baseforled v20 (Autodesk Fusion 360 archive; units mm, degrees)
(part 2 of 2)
sketch "Sketch68" plane through (0, 0, 4.5985) normal (0, 0, -1) x axis (1, 0, 0)
  line L1 (-3.9663, 41.098) -> (-0.6842, 41.0807)
  line L2 (-1.3083, -45.5462) -> (-1.3083, -48.2413)
  line L3 (-3.8307, -45.5462) -> (-1.3083, -45.5462)
  line L4 (-10.6203, -6.5447) -> (-36.7742, -6.5447)
  line L5 (-9.5157, 16.395) -> (-9.5157, 5.9667)
  line L6 (-1.1407, 19.395) -> (-6.5157, 19.395)
  line L7 (-1.1407, 39.4899) -> (-1.1407, 19.395)
  line L8 (15.6483, 40.7878) -> (15.6648, 43.898)
  line L9 (22.3093, 30.545) -> (24.7376, 30.545)
  line L10 (22.3093, 19.395) -> (22.3093, 30.545)
  line L11 (27.6843, 19.395) -> (22.3093, 19.395)
  line L12 (30.6843, -6.5447) -> (30.6843, 16.395)
  line L13 (43.6238, -6.5447) -> (30.6843, -6.5447)
  line L14 (7.6317, -45.5462) -> (10.1393, -45.5462)
  line L15 (7.6317, -48.2916) -> (7.6317, -45.5462)
  arc A1 centre (-6.1467, 43.3016) radius 3.1 clockwise from (-3.9663, 41.098) to (-9.2079, 43.7902)
  arc A2 centre (3.4248, -1.4802) radius 47 clockwise from (-1.3083, -48.2413) to (-9.2079, 43.7902)
  arc A3 centre (-3.8306, -43.6412) radius 1.905 clockwise from (-3.8307, -45.5462) to (-5.4959, -44.5664)
  arc A4 centre (3.4248, -1.4802) radius 44 clockwise from (-5.4959, -44.5664) to (-39.7156, -10.1348)
  arc A5 centre (-36.7742, -9.5447) radius 3 clockwise from (-39.7156, -10.1348) to (-36.7742, -6.5447)
  arc A6 centre (3.4248, -1.4802) radius 14.9303 clockwise from (-10.6203, -6.5447) to (-9.5157, 5.9667)
  arc A7 centre (-6.5157, 16.395) radius 3 clockwise from (-9.5157, 16.395) to (-6.5157, 19.395)
  arc A8 centre (1.8593, 39.4899) radius 3 clockwise from (-1.1407, 39.4899) to (-0.6842, 41.0807)
  arc A9 centre (3.4248, -1.4802) radius 44 clockwise from (15.6483, 40.7878) to (26.297, 36.1078)
  arc A10 centre (24.7376, 33.545) radius 3 clockwise from (26.297, 36.1078) to (24.7376, 30.545)
  arc A11 centre (27.6843, 16.395) radius 3 clockwise from (27.6843, 19.395) to (30.6843, 16.395)
  arc A12 centre (43.6238, -9.5447) radius 3 clockwise from (43.6238, -6.5447) to (46.5652, -10.1348)
  arc A13 centre (3.4248, -1.4802) radius 44 clockwise from (46.5652, -10.1348) to (11.7301, -44.6893)
  arc A14 centre (10.1393, -43.6412) radius 1.905 clockwise from (11.7301, -44.6893) to (10.1393, -45.5462)
  arc A15 centre (3.4248, -1.4802) radius 47 clockwise from (15.6648, 43.898) to (7.6317, -48.2916)
  arc A16 centre (3.4248, -1.4802) radius 44 clockwise from (26.297, 36.1078) to (46.5652, -10.1348)
  arc A17 centre (3.4248, -1.4802) radius 38 clockwise from (23.8793, 30.545) to (41.0858, -6.5447)
  arc A18 centre (38.2354, -1.552) radius 60 clockwise from (-21.5565, -6.5447) to (-3.9663, 41.098)
  arc A19 centre (38.2354, -1.552) radius 66 clockwise from (-27.5755, -6.5447) to (-8.9761, 44.5683)
  arc A20 centre (-6.1467, 43.3016) radius 3.1 clockwise from (-8.8639, 41.8094) to (-8.3271, 45.5052)
  arc A21 centre (-6.1467, 43.3016) radius 3.1 clockwise from (-9.2079, 43.7902) to (-8.3271, 45.5052)
  arc A22 centre (-6.1467, 43.3016) radius 3.1 clockwise from (-3.9663, 41.098) to (-9.2079, 43.7902)
  arc A23 centre (-6.1467, 43.3016) radius 3.1 clockwise from (-3.9663, 41.098) to (-8.8639, 41.8094)
  point P25 (26.297, 36.1078)
  point P44 (26.297, 36.1078)
  point P36 (46.5652, -10.1348)
  point P43 (46.5652, -10.1348)
  point P46 (23.8793, 30.545)
  point P47 (41.0858, -6.5447)
  point P50 (-21.5565, -6.5447)
  point P3 (-3.9663, 41.098)
  point P49 (-3.9663, 41.098)
  point P53 (-27.5755, -6.5447)
  point P52 (-8.9761, 44.5683)
  tangent A9 A16
  coincident P25 P44
  coincident P36 P43
  concentric A16 A17
  coincident L9 P46
  coincident L13 P47
  tangent A1 A18
  coincident L4 P50
  coincident P3 P49
  concentric A18 A19
  coincident L4 P53
  coincident A1 P52
  dimension "d470" distance A16 A17 = 6
  dimension "d471" distance A18 A19 = 6
  dimension "d472" radius A18 = 60
extrude "Extrude36" sketch "Sketch68" profile of A1 A2 L4 A10 L9 L13 A12 A16 A17 A18 A19 A20 A21 A22 A23 blind -5.8
sketch "Sketch70" plane through (0, 0, 89.597) normal (0, 0, 1) x axis (-1, 0, 0)
  curve K1 (-0.0797, -3.4063) -> (-5.8098, -5.6112)
  curve K2 (-5.8098, -5.6112) -> (-6.7654, 0.4537)
  arc A1 centre (-3.4248, -1.4802) radius 3.86 clockwise from (-6.7654, 0.4537) to (-0.0797, -3.4063)
  circle C1 centre (-3.4248, -1.4802) radius 1.5
  circle C2 centre (-6.1985, -2.0551) radius 0.5
  circle C3 centre (-5.4873, -3.3373) radius 0.5
  circle C4 centre (-4.2656, -4.0902) radius 0.5
  dimension "d478" diameter C2 = 1
  dimension "d479" diameter C3 = 1
  dimension "d480" diameter C4 = 1
extrude "Extrude6" cut sketch "Sketch70" profile of C2 C3 C4 against normal blind 68
sketch "Sketch71" plane through (0, 0, 33.597) normal (0, 0, -1) x axis (1, 0, 0)
  circle C1 centre (9.1523, 8.2134) radius 1.5
extrude "Extrude7" cut of existing geometry blind -0.2
sketch "Sketch72" plane through (0, 0, 33.597) normal (0, 0, -1) x axis (1, 0, 0)
  circle C1 centre (9.1523, -10.8392) radius 1.5
  circle C2 centre (9.1523, -10.8392) radius 3.64
  circle C3 centre (9.1523, -10.8392) radius 2.64
  concentric C1 C2
  concentric C2 C3
  dimension "d490" diameter C2 = 7.28
  dimension "d491" diameter C3 = 5.28
extrude "Extrude8" add sketch "Sketch72" profile of C2 C3 against normal blind 4
extrude "Extrude9" cut of existing geometry blind -3.2
extrude "Extrude10" cut of existing geometry blind -3.2
extrude "Extrude11" cut sketch "Sketch71" against normal blind 3.2
sketch "Sketch73" plane through (0, 0, 36.797) normal (0, 0, -1) x axis (1, 0, 0)
  circle C1 centre (-7.3477, -1.3129) radius 1.5
  circle C2 centre (-7.3477, -1.3129) radius 2.64
  circle C3 centre (-7.3477, -1.3129) radius 3.64
  concentric C1 C2
  concentric C2 C3
  dimension "d500" diameter C2 = 5.28
  dimension "d501" diameter C3 = 7.28
sketch "Sketch74" plane through (0, 0, 36.797) normal (0, 0, -1) x axis (1, 0, 0)
  circle C1 centre (9.1523, 8.2134) radius 1.5
  circle C2 centre (9.1523, 8.2134) radius 2.64
  circle C3 centre (9.1523, 8.2134) radius 3.64
  concentric C1 C2
  concentric C2 C3
  dimension "d502" diameter C2 = 5.28
  dimension "d503" diameter C3 = 7.28
extrude "Extrude58" new body sketch "Sketch73" profile of C2 C3 along normal blind 3.2
extrude "Extrude59" new body sketch "Sketch74" profile of C2 C3 along normal blind 3.2
extrude "Extrude60" add of existing geometry blind 2
extrude "Extrude61" add of existing geometry blind 2
extrude "Extrude12" add of existing geometry blind 2
sketch "Sketch75" plane through (0, 0, 31.597) normal (0, 0, -1) x axis (1, 0, 0)
  circle C1 centre (9.1523, -10.8392) radius 2.64
  circle C2 centre (9.1523, -10.8392) radius 3.64
  circle C3 centre (-7.3477, -1.3129) radius 3.64
  circle C4 centre (9.1523, 8.2134) radius 3.64
  circle C5 centre (9.1523, -10.8392) radius 3.64
combine "Combine4"
extrude "Extrude37" cut sketch "Sketch75" against normal blind 16
sketch "Sketch77" plane through (0, 0, 13.0985) normal (0, 0, -1) x axis (1, 0, 0)
  line L1 (30.6843, -6.5447) -> (43.6238, -6.5447)
  line L2 (17.4699, -6.5447) -> (30.6843, -6.5447)
  line L3 (-33.2828, -6.5447) -> (-10.6203, -6.5447)
  line L4 (-30.2828, -11.5447) -> (-30.2828, -9.5447)
  line L5 (-36.3207, -14.5447) -> (-33.2828, -14.5447)
  arc A1 centre (43.6238, -9.5447) radius 3 clockwise from (43.6238, -6.5447) to (46.5652, -10.1348)
  arc A2 centre (3.4248, -1.4802) radius 14.9303 clockwise from (17.4699, -6.5447) to (-10.6203, -6.5447)
  arc A3 centre (-33.2828, -9.5447) radius 3 clockwise from (-33.2828, -6.5447) to (-30.2828, -9.5447)
  arc A4 centre (-33.2828, -11.5447) radius 3 clockwise from (-30.2828, -11.5447) to (-33.2828, -14.5447)
  arc A5 centre (-36.3207, -11.5447) radius 3 clockwise from (-36.3207, -14.5447) to (-39.2289, -12.2812)
  arc A6 centre (3.4248, -1.4802) radius 44 clockwise from (46.5652, -10.1348) to (-39.2289, -12.2812)
  circle C1 centre (-19.9491, -14.8114) radius 1.5
  circle C2 centre (30.0509, -14.8114) radius 1.5
  circle C3 centre (3.7898, -34.8655) radius 3
  dimension "d521" diameter C3 = 6
extrude "Extrude39" cut sketch "Sketch77" profile of C3 against normal blind 3
sketch "Sketch78" plane through (0, 0, 16.0985) normal (0, 0, -1) x axis (1, 0, 0)
  circle C1 centre (3.7898, -34.8655) radius 3
  circle C2 centre (3.7898, -34.8655) radius 1.75
  concentric C1 C2
  dimension "d524" diameter C2 = 3.5
extrude "Extrude40" cut sketch "Sketch78" profile of C2 against normal blind 7
sketch "Sketch79" plane through (0, 0, 7.5985) normal (0, 0, -1) x axis (1, 0, 0)
  line L1 (-21.5565, -6.5447) -> (-27.5755, -6.5447)
  arc A1 centre (-6.1467, 43.3016) radius 3.1 clockwise from (-3.9663, 41.098) to (-8.9761, 44.5683)
  arc A2 centre (38.2354, -1.552) radius 66 clockwise from (-27.5755, -6.5447) to (-8.9761, 44.5683)
  arc A3 centre (38.2354, -1.552) radius 60 clockwise from (-21.5565, -6.5447) to (-3.9663, 41.098)
  circle C1 centre (-22.8691, 14.1928) radius 3
  dimension "d527" diameter C1 = 6
sketch "Sketch80" plane through (0, 0, 7.5985) normal (0, 0, -1) x axis (1, 0, 0)
  line L1 (23.8793, 30.545) -> (24.7376, 30.545)
  line L2 (43.6238, -6.5447) -> (41.0858, -6.5447)
  arc A1 centre (43.6238, -9.5447) radius 3 clockwise from (43.6238, -6.5447) to (46.5652, -10.1348)
  arc A2 centre (3.4248, -1.4802) radius 44 clockwise from (26.297, 36.1078) to (46.5652, -10.1348)
  arc A3 centre (24.7376, 33.545) radius 3 clockwise from (26.297, 36.1078) to (24.7376, 30.545)
  arc A4 centre (3.4248, -1.4802) radius 38 clockwise from (23.8793, 30.545) to (41.0858, -6.5447)
  circle C1 centre (42.8077, 9.7979) radius 3
  dimension "d528" diameter C1 = 6
extrude "Extrude41" cut sketch "Sketch80" + "Sketch79" profile of S2:A2 S2:C1 S1:A4 S1:C1 blind -10
sketch "Sketch81" plane through (0, 0, 17.5985) normal (0, 0, -1) x axis (1, 0, 0)
  arc A1 centre (-22.8691, 14.1928) radius 3 clockwise from (-25.4762, 15.6771) to (-25.8688, 14.1532)
  arc A2 centre (38.2354, -1.552) radius 66 clockwise from (-25.8688, 14.1532) to (-25.4762, 15.6771)
  circle C1 centre (-22.8691, 14.1928) radius 1.75
  concentric A1 C1
  dimension "d531" diameter C1 = 3.5
sketch "Sketch82" plane through (0, 0, 17.5985) normal (0, 0, -1) x axis (1, 0, 0)
  arc A1 centre (42.8077, 9.7979) radius 3 clockwise from (39.8344, 9.3982) to (40.0735, 8.5632)
  arc A2 centre (3.4248, -1.4802) radius 38 clockwise from (39.8344, 9.3982) to (40.0735, 8.5632)
  circle C1 centre (42.8077, 9.7979) radius 1.75
  concentric A1 C1
  dimension "d532" diameter C1 = 3.5
extrude "Extrude42" cut sketch "Sketch82" + "Sketch81" profile of S2:C1 S1:C1 blind -7
extrude "Extrude43" add of existing geometry blind 2
extrude "Extrude44" add of existing geometry blind 2
sketch "Sketch84" plane through (0, 0, 20.7985) normal (0, 0, 1) x axis (-1, 0, 0)
  line L1 (41.2893, -6.5447) -> (33.2828, -6.5447)
  line L2 (33.2828, -14.5447) -> (39.637, -14.5447)
  line L3 (30.2828, -9.5447) -> (30.2828, -11.5447)
  circle C1 centre (-42.8077, 9.7979) radius 1.75
  circle C2 centre (22.8691, 14.1928) radius 1.75
  circle C3 centre (-3.7898, -34.8655) radius 1.75
  arc A1 centre (-3.4248, -1.4802) radius 45 clockwise from (39.637, -14.5447) to (41.2893, -6.5447)
  arc A2 centre (33.2828, -11.5447) radius 3 clockwise from (33.2828, -14.5447) to (30.2828, -11.5447)
  arc A3 centre (33.2828, -9.5447) radius 3 clockwise from (30.2828, -9.5447) to (33.2828, -6.5447)
  circle C4 centre (-3.4248, -1.4802) radius 14.9303
  circle C5 centre (-3.4248, -1.4802) radius 49.8465
  circle C6 centre (-3.4248, -1.4802) radius 45
  concentric A1 C5
  concentric A1 C6
  dimension "d553" diameter C6 = 90
extrude "Extrude62" new body sketch "Sketch84" profile of A1 C5 C6 along normal blind 5 and against normal blind 5
offset_faces "OffsetFaces3" distance -0.6
shell "Shell1" innerThickness 0.4
extrude "Extrude63" add of existing geometry blind 0.1
extrude "Extrude64" add of existing geometry blind 0.1
extrude "Extrude65" cut of existing geometry blind -0.05
extrude "Extrude66" cut of existing geometry blind -0.05
offset_faces "OffsetFaces2" distance -0.05
offset_faces "OffsetFaces3" distance -0.05
offset_faces "OffsetFaces4" distance -0.05
offset_faces "OffsetFaces5" distance -0.05
offset_faces "OffsetFaces2" distance 0.4
component_insert "Component Insert15"
component_insert "Component Insert17"
component_insert "Component Insert18"
position "Position52"
as_built_joint "As-built30" OffsetX 0 OffsetY 0 OffsetZ 0 AngleZ 0
position "Position53"
step "00000000-0000-0000-0000-000000000000" TotalAngle 360
component_from_bodies "Body->Comp6"
component_from_bodies "Body->Comp7"
component_from_bodies "Body->Comp8"
component_from_bodies "Body->Comp3"
component_from_bodies "Body->Comp4"
joint "Assemble25" alignAngle 0 alignOffsetX 0 alignOffsetY 0 alignOffsetZ 0
joint "Assemble27" alignAngle -90 alignOffsetX 0 alignOffsetY 0 alignOffsetZ 7
joint "Assemble28" alignAngle 90 alignOffsetX 0 alignOffsetY 0 alignOffsetZ 0
joint "Assemble29" alignAngle 0 alignOffsetX 0 alignOffsetY 0 alignOffsetZ 0
joint "Assemble30" alignAngle -90 alignOffsetX 0 alignOffsetY 0 alignOffsetZ 0
joint "Assemble31" alignAngle -90 alignOffsetX 0 alignOffsetY 0 alignOffsetZ 0
joint "Assemble32" alignAngle 90 alignOffsetX 0 alignOffsetY 0 alignOffsetZ 0
joint "Assemble33" alignAngle 0 alignOffsetX 0 alignOffsetY 0 alignOffsetZ 0
joint "Assemble35" alignAngle 90 alignOffsetX 0 alignOffsetY 0 alignOffsetZ 0
joint "Assemble36" alignAngle 180 alignOffsetX 0 alignOffsetY 0 alignOffsetZ 0
joint "Assemble37" alignAngle 180 alignOffsetX 0 alignOffsetY 0 alignOffsetZ 0
joint "Assemble38" alignAngle 0 alignOffsetX 0 alignOffsetY 0 alignOffsetZ 0
joint "Assemble39" alignAngle 90 alignOffsetX 0 alignOffsetY 0 alignOffsetZ 0
position "Position61"
sketch "Sketch86" plane through (0, -3.5198, 0) normal (0, -1, 0) x axis (1, 0, 0)
  curve K1 (32.839, 117.5796) -> (31.473, 120.9956)
  line L1 (31.3167, 121.2295) -> (31.473, 120.9956)
  line L2 (30.9777, 116.3362) -> (28.8233, 119.5613)
  line L3 (32.839, 117.5796) -> (30.9777, 116.3362)
  arc A1 centre (29.1375, 121.7892) radius 2.25 clockwise from (28.8233, 119.5613) to (31.3167, 121.2295)
  circle C1 centre (29.1375, 121.7892) radius 1
  circle C2 centre (29.1375, 121.7892) radius 0.75
  concentric A1 C2
  dimension "d683" diameter C2 = 1.5
extrude "Extrude67" new body sketch "Sketch86" profile of C2 against normal blind 10
component_from_bodies "Body->Comp11"
as_built_joint "As-built39"
position "Position62"
as_built_joint "As-built40" OffsetX 0 OffsetY 0 OffsetZ 0 AngleZ 0
position "Position63"
sketch "Sketch87" plane through (4.6184, 2.7216, -0.1459) normal (0.8612, 0.5075, -0.0272) x axis (-0.5077, 0.8615, 0)
  curve K1 (-28.518, 121.4362) -> (-29.9164, 117.7466)
  line L1 (-28.1581, 116.5726) -> (-29.9164, 117.7466)
  line L2 (-26.0045, 119.7982) -> (-28.1581, 116.5726)
  line L3 (-28.518, 121.4362) -> (-28.4983, 121.4658)
  arc A1 centre (-26.3191, 122.0261) radius 2.25 clockwise from (-28.4983, 121.4658) to (-26.0045, 119.7982)
  circle C1 centre (-26.3191, 122.0261) radius 1
  circle C2 centre (-26.3191, 122.0261) radius 0.75
  concentric A1 C2
  dimension "d694" diameter C2 = 1.5
extrude "Extrude68" new body sketch "Sketch87" profile of C2 against normal blind 10
component_from_bodies "Body->Comp12"
joint "Assemble42" alignAngle 0 alignOffsetX 0 alignOffsetY 0 alignOffsetZ 0
position "Position64"
position "Position65"
as_built_joint "As-built42" OffsetX 0 OffsetY 0 OffsetZ 0 AngleZ 0
position "Position66"
as_built_joint "As-built43" OffsetX 0 OffsetY 0 OffsetZ 0 AngleZ 0
position "Position67"
as_built_joint "As-built44" OffsetX 0 OffsetY 0 OffsetZ 0 AngleZ 0
position "Position68"
as_built_joint "As-built45" OffsetX 0 OffsetY 0 OffsetZ 0 AngleZ 0
position "Position69"
as_built_joint "As-built46" OffsetX 0 OffsetY 0 OffsetZ 0 AngleZ 0
as_built_joint "As-built41" OffsetX 0 OffsetY 0 OffsetZ 0 AngleZ 0
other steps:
base_feature "Base Feature1"
base_feature "Base Feature1"
base_feature "Base Feature1"
base_feature "Base Feature1"
base_feature "Base Feature1"
base_feature "Base Feature1"
base_feature "Base Feature1"
base_feature "Base Feature1"
base_feature "Base Feature1"
base_feature "Base Feature1"
base_feature "Base Feature1"
base_feature "Base Feature1"
base_feature "Base Feature1"
base_feature "Base Feature1"
base_feature "Base Feature1"
derived_base_feature "Derived Base Feature1"
extrude "Extrude5" cut sketch "Sketch34" profile of C1 C2 C3 C4 C6 against normal blind 15
create_component "CreateComponent1"
create_component "CreateComponent2"
create_component "CreateComponent3"
create_component "CreateComponent4"
extrude "Extrude4" add sketch "Sketch34" profile of C1 C2 C3 C4 C6 against normal blind 15
extrude "Extrude6" add sketch "Sketch34" profile of C1 C2 C3 C4 C6 against normal blind 15
extrude "Extrude7" cut sketch "Sketch34" profile of C1 C2 C3 C4 C6 against normal blind 15
create_component "CreateComponent6"
remove_body "RemoveBody2"
create_component "CreateComponent7"
remove_body "RemoveBody3"
create_component "CreateComponent9"
remove_body "RemoveBody5"
create_component "CreateComponent10"
remove_body "RemoveBody6"
create_component "CreateComponent11"
remove_body "RemoveBody7"
create_component "CreateComponent12"
remove_body "RemoveBody8"
create_component "CreateComponent13"
remove_body "RemoveBody9"
create_component "CreateComponent14"
remove_body "RemoveBody10"
joint_origin "JointOrigin2"
joint_origin "JointOrigin2"
joint_origin "JointOrigin1"
joint_origin "JointOrigin3"
joint_origin "JointOrigin3"
joint_origin "JointOrigin6"
create_component "CreateComponent15"
joint_origin "JointOrigin1"
create_component "CreateComponent17"
extrude "Extrude8" cut sketch "Sketch63" to an object
joint_origin "JointOrigin2"
joint_origin "JointOrigin4"
remove_body "RemoveBody14"
remove_body "RemoveBody15"
create_component "CreateComponent6"
remove_body "RemoveBody6"
create_component "CreateComponent7"
remove_body "RemoveBody7"
create_component "CreateComponent8"
remove_body "RemoveBody8"
create_component "CreateComponent3"
remove_body "RemoveBody6"
create_component "CreateComponent4"
remove_body "RemoveBody7"
joint_origin "JointOrigin11"
joint_origin "JointOrigin2"
create_component "CreateComponent18"
remove_body "RemoveBody16"
create_component "CreateComponent19"
remove_body "RemoveBody17"
joint_origin "JointOrigin1"
named bodies: "Body1 (Context1)"

design "Linkage"
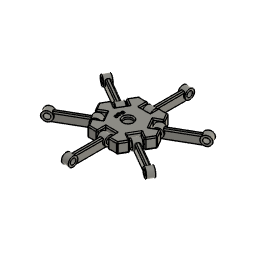
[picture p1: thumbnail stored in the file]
description: Part Number
part number: (Unsaved)
base_feature "Base Feature1"
sketch "Sketch1" plane through (0, 0, 0) normal (0, 0, 1) x axis (1, 0, 0)
  circle C1 centre (0, 0) radius 3.105
  point P1 (0, 0)
  point P2 (0, 0)
  coincident P1 P2
  dimension "d1" diameter C1 = 6.21
extrude "Extrude1" cut sketch "Sketch1" along normal blind 3
sketch "Sketch2" plane through (0, 0, 0) normal (0, 0, -1) x axis (1, 0, 0)
  line L1 (2.9678, 11.5057) -> (6.6175, 11.5127)
  line L2 (2.9678, 7.491) -> (2.9678, 11.5057)
  line L3 (-3.0322, 7.491) -> (2.9678, 7.491)
  line L4 (-3.0322, 11.4942) -> (-3.0322, 7.491)
  line L5 (-6.6616, 11.4872) -> (-3.0322, 11.4942)
  line L6 (-8.4803, 8.323) -> (-6.6616, 11.4872)
  line L7 (-5.0035, 6.3157) -> (-8.4803, 8.323)
  line L8 (-8.0035, 1.1195) -> (-5.0035, 6.3157)
  line L9 (-11.4704, 3.1211) -> (-8.0035, 1.1195)
  line L10 (-13.279, -0.0255) -> (-11.4704, 3.1211)
  line L11 (-11.4481, -3.1827) -> (-13.279, -0.0255)
  line L12 (-7.9713, -1.1753) -> (-11.4481, -3.1827)
  line L13 (-4.9713, -6.3715) -> (-7.9713, -1.1753)
  line L14 (-8.4382, -8.3731) -> (-4.9713, -6.3715)
  line L15 (-6.6175, -11.5127) -> (-8.4382, -8.3731)
  line L16 (-2.9678, -11.5057) -> (-6.6175, -11.5127)
  line L17 (-2.9678, -7.491) -> (-2.9678, -11.5057)
  line L18 (3.0322, -7.491) -> (-2.9678, -7.491)
  line L19 (3.0322, -11.4942) -> (3.0322, -7.491)
  line L20 (6.6616, -11.4872) -> (3.0322, -11.4942)
  line L21 (8.4803, -8.323) -> (6.6616, -11.4872)
  line L22 (5.0035, -6.3157) -> (8.4803, -8.323)
  line L23 (8.0035, -1.1195) -> (5.0035, -6.3157)
  line L24 (11.4704, -3.1211) -> (8.0035, -1.1195)
  line L25 (13.279, 0.0255) -> (11.4704, -3.1211)
  line L26 (11.4481, 3.1827) -> (13.279, 0.0255)
  line L27 (7.9713, 1.1753) -> (11.4481, 3.1827)
  line L28 (4.9713, 6.3715) -> (7.9713, 1.1753)
  line L29 (8.4382, 8.3731) -> (4.9713, 6.3715)
  line L30 (6.6175, 11.5127) -> (8.4382, 8.3731)
  circle C1 centre (0, 0) radius 3.105
  circle C2 centre (0, 0) radius 2.14
  concentric C1 C2
  dimension "d4" diameter C2 = 4.28
  dimension "d7" diameter C1 = 6.21
extrude "Extrude2" cut sketch "Sketch2" profile of C2 against normal blind 11
extrude "Extrude3" cut of existing geometry blind -0.2
fillet "Fillet2" radius 0.1
fillet "Fillet3" radius 0.1
extrude "Extrude4" add blind -5
sketch "Sketch5" plane through (0, 0, 10) normal (0, 0, 1) x axis (-1, 0, 0)
  circle C1 centre (0, 0) radius 2.6
  circle C2 centre (0, 0) radius 2.14
  circle C3 centre (0, 0) radius 3.1
  point P1 (0, 0)
  point P3 (0, 0)
  coincident P1 P3
  dimension "d22" diameter C3 = 6.2
extrude "Extrude6" cut sketch "Sketch5" profile of C1 C2 against normal blind 11
extrude "Extrude7" add sketch "Sketch5" profile of C1 C3 against normal blind 5
extrude "Extrude8" cut of existing geometry blind -1
offset_faces "OffsetFaces1" distance -0.5
extrude "Extrude9" add sketch "Sketch5" profile of C1 C2 against normal blind 6
sketch "Sketch6" plane through (0, 0, 0) normal (0, 0, -1) x axis (1, 0, 0)
  line L1 (2.9678, 11.5057) -> (6.6175, 11.5127)
  line L2 (2.9678, 7.491) -> (2.9678, 11.5057)
  line L3 (-3.0322, 7.491) -> (2.9678, 7.491)
  line L4 (-3.0322, 11.4942) -> (-3.0322, 7.491)
  line L5 (-6.6616, 11.4872) -> (-3.0322, 11.4942)
  line L6 (-8.4803, 8.323) -> (-6.6616, 11.4872)
  line L7 (-5.0035, 6.3157) -> (-8.4803, 8.323)
  line L8 (-8.0035, 1.1195) -> (-5.0035, 6.3157)
  line L9 (-11.4704, 3.1211) -> (-8.0035, 1.1195)
  line L10 (-13.279, -0.0255) -> (-11.4704, 3.1211)
  line L11 (-11.4481, -3.1827) -> (-13.279, -0.0255)
  line L12 (-7.9713, -1.1753) -> (-11.4481, -3.1827)
  line L13 (-4.9713, -6.3715) -> (-7.9713, -1.1753)
  line L14 (-8.4382, -8.3731) -> (-4.9713, -6.3715)
  line L15 (-6.6175, -11.5127) -> (-8.4382, -8.3731)
  line L16 (-2.9678, -11.5057) -> (-6.6175, -11.5127)
  line L17 (-2.9678, -7.491) -> (-2.9678, -11.5057)
  line L18 (3.0322, -7.491) -> (-2.9678, -7.491)
  line L19 (3.0322, -11.4942) -> (3.0322, -7.491)
  line L20 (6.6616, -11.4872) -> (3.0322, -11.4942)
  line L21 (8.4803, -8.323) -> (6.6616, -11.4872)
  line L22 (5.0035, -6.3157) -> (8.4803, -8.323)
  line L23 (8.0035, -1.1195) -> (5.0035, -6.3157)
  line L24 (11.4704, -3.1211) -> (8.0035, -1.1195)
  line L25 (13.279, 0.0255) -> (11.4704, -3.1211)
  line L26 (11.4481, 3.1827) -> (13.279, 0.0255)
  line L27 (7.9713, 1.1753) -> (11.4481, 3.1827)
  line L28 (4.9713, 6.3715) -> (7.9713, 1.1753)
  line L29 (8.4382, 8.3731) -> (4.9713, 6.3715)
  line L30 (6.6175, 11.5127) -> (8.4382, 8.3731)
  circle C1 centre (0, 0) radius 3.705
  circle C2 centre (0, 0) radius 5
  circle C3 centre (0, 0) radius 6
  point P1 (0, 0)
  point P33 (0, 0)
  point P34 (0, 0)
  coincident P1 P33
  coincident P1 P34
  dimension "d32" diameter C2 = 10
  dimension "d33" diameter C3 = 12
extrude "Extrude10" add sketch "Sketch6" profile of C2 C3 along normal blind 2
extrude "Extrude11" cut of existing geometry blind -5
offset_faces "OffsetFaces2" distance 0.05
extrude "Extrude12" add of existing geometry blind 0.2
extrude "Extrude13" add of existing geometry blind 0.3
fillet "Fillet4" radius 1
sketch "Sketch7" plane through (0, 0, 0) normal (0, 0, -1) x axis (1, 0, 0)
  line L1 (0, 0) -> (-5, 0)
  circle C1 centre (0, 0) radius 5
  circle C2 centre (0, 0) radius 3.705
  circle C3 centre (-4.3, 0) radius 0.5
  circle C4 centre (0, 0) radius 4.3
  circle C5 centre (-4.0423, 1.4662) radius 0.5
  circle C6 centre (-4.0224, -1.5199) radius 0.5
  point P4 (-5, 0)
  point P1 (0, 0)
  point P5 (0, 0)
  point P3 (-4.3, 0)
  point P6 (0, 0)
  point P7 (-4.0423, 1.4662)
  point P8 (-4.0224, -1.5199)
  coincident C1 P4
  coincident P1 P5
  horizontal L1
  coincident P3 L1
  coincident P1 P6
  coincident P3 C4
  coincident C4 P7
  coincident C4 P8
  dimension "d45" diameter C3 = 1
  dimension "d46" diameter C5 = 1
  dimension "d47" diameter C6 = 1
  dimension "d48" diameter C4 = 8.6
extrude "Extrude14" cut sketch "Sketch7" profile of C3 C5 C6 against normal blind 5
fillet "Fillet5" radius 1
fillet "Fillet6" radius 1
fillet "Fillet7" radius 0.5
fillet "Fillet8" radius 0.25
component_from_bodies "Body->Comp1"
component_from_bodies "Body->Comp2"
component_from_bodies "Body->Comp3"
component_from_bodies "Body->Comp4"
component_from_bodies "Body->Comp5"
component_from_bodies "Body->Comp6"
component_from_bodies "Body->Comp7"
joint "Assemble1" alignAngle 0 alignOffsetX 0 alignOffsetY 0 alignOffsetZ 0
joint "Assemble2" alignAngle 0 alignOffsetX 0 alignOffsetY 0 alignOffsetZ 0
joint "Assemble3" alignAngle 0 alignOffsetX 0 alignOffsetY 0 alignOffsetZ 0
joint "Assemble4" alignAngle 0 alignOffsetX 0 alignOffsetY 0 alignOffsetZ 0
joint "Assemble5" alignAngle 0 alignOffsetX 0 alignOffsetY 0 alignOffsetZ 0
joint "Assemble6" alignAngle 0 alignOffsetX 0 alignOffsetY 0 alignOffsetZ 0
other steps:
base_feature "Base Feature1"
base_feature "Base Feature1"
base_feature "Base Feature1"
base_feature "Base Feature1"
base_feature "Base Feature1"
base_feature "Base Feature1"
base_feature "Base Feature1"
create_component "CreateComponent1"
remove_body "RemoveBody1"
create_component "CreateComponent2"
remove_body "RemoveBody2"
create_component "CreateComponent3"
remove_body "RemoveBody3"
create_component "CreateComponent4"
remove_body "RemoveBody4"
create_component "CreateComponent5"
remove_body "RemoveBody5"
create_component "CreateComponent6"
remove_body "RemoveBody6"
create_component "CreateComponent7"
remove_body "RemoveBody7"
joint_origin "JointOrigin1"
joint_origin "JointOrigin1"
joint_origin "JointOrigin1"
joint_origin "JointOrigin2"
joint_origin "JointOrigin1"
joint_origin "JointOrigin3"
joint_origin "JointOrigin1"
joint_origin "JointOrigin4"
joint_origin "JointOrigin1"
joint_origin "JointOrigin5"
joint_origin "JointOrigin1"
joint_origin "JointOrigin6"

design "Petal"
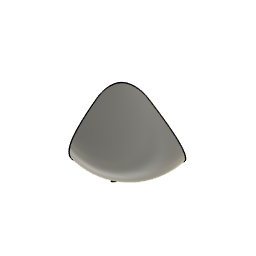
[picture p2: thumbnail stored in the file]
description: Part Number
part number: week16petal (v2~recovered)
part number: Component2
base_feature "Base Feature"
sketch "Sketch1" plane through (4.9276, 5.0138, 0.2465) normal (0.7005, 0.7128, 0.035) x axis (-0.7132, 0.701, 0)
  line L1 (-24.6216, 3.8742) -> (-23.6437, 2.1209)
  line L2 (-26.9345, 2.5843) -> (-24.6216, 3.8742)
  curve K1 (-26.9345, 2.5843) -> (-27.2041, 0.4469)
  curve K2 (-27.204, 0.4472) -> (-25.4706, 0.4091)
  line L3 (-25.4706, 0.4091) -> (-24.856, -0.3808)
  line L4 (-25.1105, -0.5813) -> (-24.856, -0.3808)
  curve K3 (-25.1105, -0.5813) -> (-26.6209, -0.5991)
  line L5 (-24.1132, -5.0954) -> (-26.6209, -0.5991)
  line L6 (-21.4, -5.7004) -> (-21.5964, -5.8099)
  line L7 (-23.6438, 2.1208) -> (-20.6855, -3.1836)
  arc A1 centre (-22.4975, -4.1942) radius 1.85 clockwise from (-21.5964, -5.8099) to (-24.1132, -5.0954)
  arc A2 centre (-22.3012, -4.0847) radius 1.85 clockwise from (-20.6855, -3.1836) to (-21.4, -5.7004)
  circle C1 centre (-22.1794, -4.3844) radius 1
  circle C2 centre (-22.1794, -4.3844) radius 1
  concentric C1 C2
  dimension "d1" diameter C2 = 2
extrude "Extrude1" new body sketch "Sketch1" profile of C1 C2 against normal blind 14 and along normal blind 1
combine "Combine1"
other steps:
create_component "CreateComponent1"

design "sensormountnyt1"
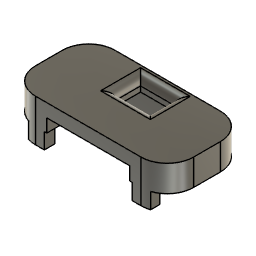
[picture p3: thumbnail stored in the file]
sketch "Sketch1" plane through (0, 0, 0) normal (0, 0, 1) x axis (1, 0, 0)
  line L1 (-46.0372, 3.5704) -> (-71.1272, 3.5704)
  line L2 (-50.7072, 8.9454) -> (-66.4572, 8.9454)
  line L3 (-50.7072, -1.8046) -> (-50.7072, 8.9454)
  line L4 (-66.4572, -1.8046) -> (-50.7072, -1.8046)
  line L5 (-66.4572, 8.9454) -> (-66.4572, -1.8046)
  line L6 (-58.5822, -10) -> (-58.5822, 14)
  line L7 (-51.3998, 6.2954) -> (-48.6897, 6.2954)
  line L8 (-51.3998, 0.9) -> (-51.3998, 6.2954)
  line L9 (-48.4262, 0.9) -> (-51.3998, 0.9)
  line L10 (-65.6694, 6.294) -> (-68.2998, 6.294)
  line L11 (-65.6694, 0.8578) -> (-65.6694, 6.294)
  line L12 (-68.3745, 0.8454) -> (-65.6694, 0.8578)
  line L13 (-55.3646, 8.0889) -> (-61.7998, 8.0889)
  line L14 (-55.3646, 4) -> (-55.3646, 8.0889)
  line L15 (-61.7998, 4) -> (-55.3646, 4)
  line L16 (-61.7998, 8.0889) -> (-61.7998, 4)
  line L17 (-43.5822, 9.0367) -> (-73.5822, 9.0367)
  line L18 (-43.5822, -6.0533) -> (-43.5822, 9.0367)
  line L19 (-73.5822, -6.0533) -> (-43.5822, -6.0533)
  line L20 (-73.5822, 9.0367) -> (-73.5822, -6.0533)
  line L21 (-67.0087, 9.0367) -> (-71.0087, 9.0367)
  line L22 (-67.0087, 7.0367) -> (-67.0087, 9.0367)
  line L23 (-71.0087, 7.0367) -> (-67.0087, 7.0367)
  line L24 (-71.0087, 9.0367) -> (-71.0087, 7.0367)
  line L25 (-66.9192, -6.0533) -> (-70.9192, -6.0533)
  line L26 (-66.9192, -4.0533) -> (-66.9192, -6.0533)
  line L27 (-70.9192, -4.0533) -> (-66.9192, -4.0533)
  line L28 (-70.9192, -6.0533) -> (-70.9192, -4.0533)
  line L29 (-46.1558, 7.0367) -> (-50.1558, 7.0367)
  line L30 (-50.1558, 7.0367) -> (-50.1558, 9.0367)
  line L31 (-50.1558, 9.0367) -> (-46.1558, 9.0367)
  line L32 (-46.1558, 9.0367) -> (-46.1558, 7.0367)
  line L33 (-50.2453, -4.0533) -> (-50.2453, -6.0533)
  line L34 (-46.2453, -4.0533) -> (-50.2453, -4.0533)
  line L35 (-46.2453, -6.0533) -> (-46.2453, -4.0533)
  line L36 (-50.2453, -6.0533) -> (-46.2453, -6.0533)
  circle C1 centre (-48.6897, 3.5704) radius 2.725
  circle C2 centre (-68.387, 3.5704) radius 2.725
  point P10 (-48.6897, 3.5704)
  point P11 (-68.387, 3.5704)
  point P2 (-71.1272, 3.5704)
  point P3 (-46.0372, 3.5704)
  point P12 (-48.6897, 6.2954)
  point P16 (-68.2998, 6.294)
  point P19 (-68.3745, 0.8454)
  point P28 (-71.0087, 9.0367)
  point P32 (-70.9192, -6.0533)
  point P39 (-46.1558, 9.0367)
  point P29 (-67.0087, 9.0367)
  point P38 (-50.1558, 9.0367)
  point P30 (-67.0087, 7.0367)
  point P36 (-50.1558, 7.0367)
  point P31 (-71.0087, 7.0367)
  point P37 (-46.1558, 7.0367)
  point P43 (-46.2453, -6.0533)
  point P33 (-66.9192, -6.0533)
  point P40 (-50.2453, -6.0533)
  point P34 (-66.9192, -4.0533)
  point P41 (-50.2453, -4.0533)
  point P35 (-70.9192, -4.0533)
  point P42 (-46.2453, -4.0533)
  point P4 (-66.4572, 8.9454)
  point P5 (-50.7072, 8.9454)
  point P7 (-66.4572, -1.8046)
  point P24 (-73.5822, 9.0367)
  point P25 (-43.5822, 9.0367)
  point P27 (-73.5822, -6.0533)
  horizontal L1
  horizontal L2
  vertical L3
  horizontal L4
  vertical L5
  symmetric L1 L2 L4
  vertical L6
  symmetric L3 L5 L6
  coincident L1 P10
  coincident L1 P11
  symmetric P2 P3 L6
  coincident C1 P12
  tangent C1 L7
  perpendicular L3 L7
  perpendicular L1 L8
  perpendicular L8 L9
  coincident C2 P16
  perpendicular L5 L10
  perpendicular L10 L11
  coincident C2 P19
  tangent C2 L12
  horizontal L13
  vertical L14
  horizontal L15
  vertical L16
  horizontal L17
  vertical L18
  horizontal L19
  vertical L20
  symmetric L6 L18 L20
  horizontal L21
  vertical L22
  horizontal L23
  vertical L24
  coincident L17 P28
  horizontal L25
  vertical L26
  horizontal L27
  vertical L28
  coincident L19 P32
  symmetric L6 P28 P39
  symmetric L6 P29 P38
  symmetric L6 P30 P36
  symmetric L6 P31 P37
  symmetric L6 P32 P43
  symmetric L6 P33 P40
  symmetric L6 P34 P41
  symmetric L6 P35 P42
  symmetric L6 L14 L16
  dimension "d1" distance P2 P3 = 25.09
  dimension "d2" distance P4 P5 = 15.75
  dimension "d3" distance P4 P7 = 10.75
  dimension "d4" diameter C1 = 5.45
  dimension "d5" diameter C2 = 5.45
  dimension "d6" distance P24 P25 = 30
  dimension "d7" distance P24 P27 = 15.09
  dimension "d8" distance P28 P29 = 4
  dimension "d9" distance P28 P31 = 2
  dimension "d10" distance P32 P33 = 4
  dimension "d11" distance P32 P35 = 2
extrude "Extrude1" new body sketch "Sketch1" profile of L2 L3 L4 L5 C1 C2 L7 L8 L9 L10 L11 L12 L13 L14 L15 L16 L17 L18 L19 L20 L21 L22 L23 L24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 along normal blind 5
extrude "Extrude2" cut sketch "Sketch1" profile of L13 L14 L15 L16 along normal blind 11
extrude "Extrude3" cut sketch "Sketch1" profile of L2 L3 L4 L5 C1 C2 L7 L8 L9 L10 L11 L12 L13 L14 L15 L16 along normal blind 2.5
extrude "Extrude4" cut of existing geometry blind -6
extrude "Extrude5" add sketch "Sketch1" profile of L17 L19 L21 L22 L23 L24 L25 L26 L27 L28 L29 L30 L31 L32 L33 L34 L35 L36 against normal blind 3
extrude "Extrude6" add of existing geometry blind 1
extrude "Extrude7" cut of existing geometry blind -1
extrude "Extrude8" add of existing geometry blind 1
extrude "Extrude9" add of existing geometry blind 1
extrude "Extrude10" add of existing geometry blind 0.01
extrude "Extrude11" add of existing geometry blind 0.04
extrude "Extrude13" cut of existing geometry blind -0.75
extrude "Extrude14" cut of existing geometry blind -0.75
extrude "Extrude15" cut of existing geometry blind -0.75
extrude "Extrude16" cut of existing geometry blind -0.75
fillet "Fillet2" radius 5
sketch "Sketch2" plane through (0, 0, 0) normal (0, 0, -1) x axis (1, 0, 0)
  line L1 (-43.5822, 0.0533) -> (-43.5822, -5.0367)
  line L2 (-50.2453, 3.0533) -> (-46.9953, 3.0533)
  line L3 (-50.2453, 5.0533) -> (-50.2453, 3.0533)
  line L4 (-50.7072, 5.0533) -> (-50.2453, 5.0533)
  line L5 (-50.7072, -0.9) -> (-50.7072, 5.0533)
  line L6 (-49.2325, -0.9) -> (-50.7072, -0.9)
  line L7 (-50.7072, -6.2954) -> (-48.6897, -6.2954)
  line L8 (-50.7072, -8.9454) -> (-50.7072, -6.2954)
  line L9 (-66.4572, -8.9454) -> (-50.7072, -8.9454)
  line L10 (-66.4572, -6.294) -> (-66.4572, -8.9454)
  line L11 (-68.2998, -6.294) -> (-66.4572, -6.294)
  line L12 (-66.4572, -0.8542) -> (-68.3745, -0.8454)
  line L13 (-66.4572, 5.0533) -> (-66.4572, -0.8542)
  line L14 (-66.9192, 5.0533) -> (-66.4572, 5.0533)
  line L15 (-66.9192, 3.0533) -> (-66.9192, 5.0533)
  line L16 (-70.1692, 3.0533) -> (-66.9192, 3.0533)
  line L17 (-73.5822, -5.0367) -> (-73.5822, 0.0533)
  line L18 (-67.0087, -7.0367) -> (-70.2587, -7.0367)
  line L19 (-67.0087, -10.0367) -> (-67.0087, -7.0367)
  line L20 (-50.1558, -10.0367) -> (-67.0087, -10.0367)
  line L21 (-50.1558, -7.0367) -> (-50.1558, -10.0367)
  line L22 (-46.9058, -7.0367) -> (-50.1558, -7.0367)
  line L23 (-67.0087, -10.0367) -> (-50.1558, -10.0367)
  line L24 (-67.0087, -8.9454) -> (-67.0087, -10.0367)
  line L25 (-50.1558, -8.9454) -> (-67.0087, -8.9454)
  line L26 (-50.1558, -10.0367) -> (-50.1558, -8.9454)
  line L27 (-46.9953, 3.0533) -> (-46.9953, 4.7948)
  line L28 (-70.1692, 4.7948) -> (-70.1692, 3.0533)
  line L29 (-70.2587, -7.0367) -> (-70.2587, -9.7472)
  line L30 (-46.9058, -9.7472) -> (-46.9058, -7.0367)
  arc A1 centre (-48.5822, -5.0367) radius 5 clockwise from (-43.5822, -5.0367) to (-46.9058, -9.7472)
  arc A2 centre (-48.5822, 0.0533) radius 5 clockwise from (-46.9953, 4.7948) to (-43.5822, 0.0533)
  arc A3 centre (-48.6897, -3.5704) radius 2.725 clockwise from (-49.2325, -0.9) to (-48.6897, -6.2954)
  arc A4 centre (-68.387, -3.5704) radius 2.725 clockwise from (-68.2998, -6.294) to (-68.3745, -0.8454)
  arc A5 centre (-68.5822, 0.0533) radius 5 clockwise from (-73.5822, 0.0533) to (-70.1692, 4.7948)
  arc A6 centre (-68.5822, -5.0367) radius 5 clockwise from (-70.2587, -9.7472) to (-73.5822, -5.0367)
  point P42 (-67.0087, -8.9454)
  point P37 (-50.1558, -10.0367)
  point P40 (-50.1558, -10.0367)
  horizontal L23
  vertical L24
  horizontal L25
  vertical L26
  coincident L19 P42
  coincident P37 P40
extrude "Extrude12" add sketch "Sketch2" profile of L9 L19 L20 L21 L23 L24 L25 L26 along normal blind 2
extrude "Extrude17" cut of existing geometry blind -0.5
fillet "Fillet3" radius 1.5

design "cup"
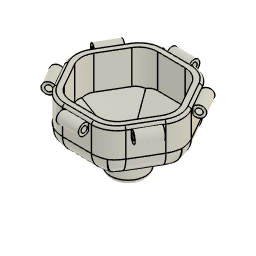
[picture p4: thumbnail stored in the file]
description: Part Number
part number: Untitled
parameter "d13" = 0
parameter "d14" = 10
derived_context "DerivedContext1"
derived_context "DerivedContext2"
base_feature "Base Feature1"
remove_body "RemoveBody1"
extrude "Extrude10" add of existing geometry blind 3
extrude "Extrude11" add of existing geometry blind 3
extrude "Extrude12" add of existing geometry blind 3
sketch "Sketch5" plane through (0, 0, -30) normal (0, 0, -1) x axis (1, 0, 0)
  circle C1 centre (0, 0) radius 5.04
  circle C2 centre (0, 0) radius 7
  circle C3 centre (0, 0) radius 6.0828
  point P1 (0, 0)
  point P3 (0, 0)
  coincident P1 P3
extrude "Extrude13" add sketch "Sketch5" profile of C1 against normal blind 8
combine "Combine3"
offset_faces "OffsetFaces2" distance -0.2
remove_body "RemoveBody2"
fillet "Fillet1" radius 2
remove_body "RemoveBody3"
remove_body "RemoveBody4"
remove_body "RemoveBody5"
remove_body "RemoveBody6"
remove_body "RemoveBody7"
remove_body "RemoveBody8"
component_from_bodies "Body->Comp"
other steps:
base_feature "Base Feature1"
derived_base_feature "Derived Base Feature"
create_component "CreateComponent1"
remove_body "RemoveBody9"

design "linkagestopper"
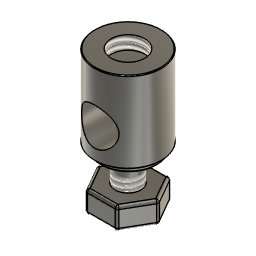
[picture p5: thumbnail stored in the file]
sketch "Sketch1" plane through (0, 0, 0) normal (0, 1, 0) x axis (1, 0, 0)
sketch "Sketch2" plane through (0, 0, 0) normal (0, 0, 1) x axis (1, 0, 0)
  line L1 (2.3094, 0) -> (1.1547, -2)
  line L2 (1.1547, 2) -> (2.3094, 0)
  line L3 (-1.1547, 2) -> (1.1547, 2)
  line L4 (-2.3094, 0) -> (-1.1547, 2)
  line L5 (-1.1547, -2) -> (-2.3094, 0)
  line L6 (1.1547, -2) -> (-1.1547, -2)
  point P1 (0, 0)
  point P8 (0, 0)
  coincident P1 P8
extrude "Extrude1" new body sketch "Sketch2" along normal blind 1.62
sketch "Sketch3" plane through (0, 0, 1.62) normal (0, 0, 1) x axis (-1, 0, 0)
  line L1 (-1.1547, 2) -> (1.1547, 2)
  line L2 (-2.3094, 0) -> (-1.1547, 2)
  line L3 (-1.1547, -2) -> (-2.3094, 0)
  line L4 (1.1547, -2) -> (-1.1547, -2)
  line L5 (2.3094, 0) -> (1.1547, -2)
  line L6 (1.1547, 2) -> (2.3094, 0)
  circle C1 centre (0, 0) radius 0.94
  point P1 (0, 0)
  point P8 (0, 0)
  coincident P1 P8
  dimension "d4" diameter C1 = 1.88
extrude "Extrude2" add sketch "Sketch3" profile of C1 along normal blind 2.64
sketch "Sketch4" plane through (0, 0, 4.26) normal (0, 0, 1) x axis (-1, 0, 0)
  circle C1 centre (0, 0) radius 0.94
  circle C2 centre (0, 0) radius 2.125
  circle C3 centre (0, 0) radius 1.1
  concentric C1 C2
  concentric C2 C3
  dimension "d7" diameter C2 = 4.25
  dimension "d8" diameter C3 = 2.2
extrude "Extrude3" new body sketch "Sketch4" profile of C2 C3 along normal blind 0.51
move "Move1"
sketch "Sketch5" plane through (0, 0, 4.26) normal (0, 0, 1) x axis (-1, 0, 0)
  circle C1 centre (0, 0) radius 0.94
  circle C2 centre (0, 0) radius 2.5
  point P1 (0, 0)
  point P3 (0, 0)
  coincident P1 P3
  dimension "d11" diameter C2 = 5
extrude "Extrude4" add sketch "Sketch5" along normal blind 6.06
sketch "Sketch6" plane through (0, -2, 0) normal (0, -1, 0) x axis (1, 0, 0)
  line L1 (1.1547, 0) -> (-1.1547, 0)
  line L2 (1.1547, 1.62) -> (1.1547, 0)
  line L3 (-1.1547, 1.62) -> (1.1547, 1.62)
  line L4 (-1.1547, 0) -> (-1.1547, 1.62)
  line L5 (-0.0048, 5.6982) -> (-0.0048, 4.2582)
  circle C1 centre (0, 6.5) radius 0.9
  point P6 (-0.0048, 4.2582)
  point P7 (-0.0048, 5.6982)
  vertical L5
  dimension "d14" distance P6 P7 = 1.44
  dimension "d15" diameter C1 = 1.8
extrude "Extrude5" cut sketch "Sketch6" profile of C1 against normal blind 15.5
extrude "Extrude6" cut of existing geometry blind -4
thread "Thread1" ThreadOffset 0 ThreadLength 1
sketch "Sketch7" plane through (0, 0, 10.32) normal (0, 0, 1) x axis (-1, 0, 0)
  circle C1 centre (0, 0) radius 2.5
  circle C2 centre (0, 0) radius 1.55
  point P1 (0, 0)
  point P3 (0, 0)
  coincident P1 P3
  dimension "d22" diameter C2 = 3.1
extrude "Extrude7" cut sketch "Sketch7" profile of C2 against normal blind 1
thread "Thread2" ThreadOffset 0 ThreadLength 10
sketch "Sketch8" plane through (0, 0, 0) normal (0, 0, -1) x axis (1, 0, 0)
  line L1 (-1.1547, 2) -> (1.1547, 2)
  line L2 (-2.3094, 0) -> (-1.1547, 2)
  line L3 (-1.1547, -2) -> (-2.3094, 0)
  line L4 (1.1547, -2) -> (-1.1547, -2)
  line L5 (2.3094, 0) -> (1.1547, -2)
  line L6 (1.1547, 2) -> (2.3094, 0)
  circle C1 centre (0, 0) radius 1.1748
  point P1 (0, 0)
  point P8 (0, 0)
  coincident P1 P8
extrude "Extrude8" cut sketch "Sketch8" profile of C1 against normal blind 0.5
fillet "Fillet1" radius 0.2
fillet "Fillet2" radius 0.1
fillet "Fillet3" radius 0.05
move "Move2"
component_from_bodies "Body->Comp1"
component_from_bodies "Body->Comp2"
offset_faces "OffsetFaces1" distance -0.5
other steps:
base_feature "Base Feature1"
base_feature "Base Feature1"
create_component "CreateComponent1"
remove_body "RemoveBody1"
create_component "CreateComponent2"
remove_body "RemoveBody2"

design "Tower Pro MG90S Micro servo"
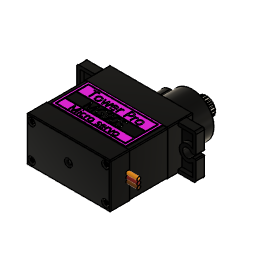
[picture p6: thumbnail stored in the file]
description: STEP AP214
part number: Tower Pro MG90S Micro servo
base_feature "Base Feature" AlongDistance 3.5 TaperAngle 0 AlongDistance 3 TaperAngle 0

design "Seervo-horn"
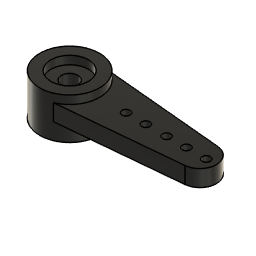
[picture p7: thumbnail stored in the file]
sketch "Sketch1" plane through (0, 0, 0) normal (0, 0, 1) x axis (1, 0, 0)
  line L1 (19.646, 0.0135) -> (-1.824, 0.0135)
  circle C1 centre (1.8209, 0) radius 3.645
  circle C2 centre (1.8209, 0) radius 2.27
  point P4 (-1.824, 0.0135)
  point P5 (19.646, 0.0135)
  concentric C1 C2
  coincident C1 P4
  horizontal L1
  dimension "d2" diameter C1 = 7.29
  dimension "d3" diameter C2 = 4.54
  dimension "d7" distance P4 P5 = 21.47
extrude "Extrude1" new body sketch "Sketch1" profile of C1 C2 along normal blind 2
sketch "Sketch3" plane through (0, 0, 2) normal (0, 0, 1) x axis (-1, 0, 0)
  line L1 (-19.646, -0.0135) -> (1.824, -0.0135)
  circle C1 centre (-1.8209, 0) radius 2.27
  circle C2 centre (-1.8209, 0) radius 3.645
  circle C3 centre (-1.8209, 0) radius 1
  concentric C1 C3
  dimension "d9" diameter C3 = 2
sketch "Sketch5" plane through (0, 0, 2) normal (0, 0, 1) x axis (1, 0, 0)
sketch "Sketch6" plane through (0, 0, 2) normal (0, 0, 1) x axis (-1, 0, 0)
  line L1 (-3.1004, -3.372) -> (-3.1004, 3.3796)
  line L2 (-17.8312, -2.0135) -> (-17.8312, 1.9865)
  line L3 (-19.646, -0.0135) -> (1.824, -0.0135)
  line L4 (-17.8312, -2.0135) -> (-3.1004, -3.372)
  line L5 (-17.8312, 1.9865) -> (-3.1004, 3.3796)
  arc A1 centre (-17.642, -0.0135) radius 2.0089 clockwise from (-17.8312, -2.0135) to (-17.8312, 1.9865)
  point P4 (-17.8312, 1.9865)
  point P5 (-17.8312, -2.0135)
  vertical L1
  vertical L2
  symmetric P4 P5 L3
  tangent L5 A1
  dimension "d10" distance P4 P5 = 4
extrude "Extrude2" add sketch "Sketch6" + "Sketch3" blind 2
sketch "Sketch8" plane through (0, 0, 4) normal (0, 0, 1) x axis (-1, 0, 0)
  line L1 (-17.8312, 1.9865) -> (-3.2121, 3.3691)
  line L2 (-3.235, -3.3596) -> (-17.8312, -2.0135)
  arc A1 centre (-17.642, -0.0135) radius 2.0089 clockwise from (-17.8312, -2.0135) to (-17.8312, 1.9865)
  arc A2 centre (-1.8209, 0) radius 3.645 clockwise from (-3.2121, 3.3691) to (-3.235, -3.3596)
  circle C1 centre (-1.8209, 0) radius 1
  circle C2 centre (-1.8209, 0) radius 3.645
  circle C3 centre (-1.8209, 0) radius 2.2815
  concentric A2 C2
  concentric C2 C3
  dimension "d20" diameter C3 = 4.563
extrude "Extrude3" add sketch "Sketch8" profile of A2 C2 C3 along normal blind 1
sketch "Sketch9" plane through (0, 0, 4) normal (0, 0, 1) x axis (-1, 0, 0)
  line L1 (-17.8312, 1.9865) -> (-3.2121, 3.3691)
  line L2 (-3.235, -3.3596) -> (-17.8312, -2.0135)
  arc A1 centre (-1.8209, 0) radius 3.645 clockwise from (-3.235, -3.3596) to (-3.2121, 3.3691)
  arc A2 centre (-17.642, -0.0135) radius 2.0089 clockwise from (-17.8312, -2.0135) to (-17.8312, 1.9865)
  circle C1 centre (-8.69, 0.0035) radius 0.5
  circle C2 centre (-13.6244, 0.0162) radius 0.5
  circle C3 centre (-11.0975, 0.0191) radius 0.5
  circle C4 centre (-16.0144, 0.0002) radius 0.5
  circle C5 centre (-18.4313, 0.0018) radius 0.5
  dimension "d15" diameter C1 = 1
  dimension "d16" diameter C2 = 1
  dimension "d17" diameter C3 = 1
  dimension "d18" diameter C4 = 1
  dimension "d19" diameter C5 = 1
sketch "Sketch10" plane through (0, 0, 4) normal (0, 0, 1) x axis (-1, 0, 0)
  line L1 (-8.2026, 0.0043) -> (-4.1026, 0.0043)
  point P2 (-4.1026, 0.0043)
  point P3 (-8.2026, 0.0043)
  horizontal L1
  dimension "d21" distance P2 P3 = 4.1
sketch "Sketch11" plane through (0, 0, 4) normal (0, 0, 1) x axis (-1, 0, 0)
  line L1 (-10.5455, -0.0122) -> (-9.2055, -0.0122)
  point P2 (-9.2055, -0.0122)
  point P3 (-10.5455, -0.0122)
  horizontal L1
  dimension "d22" distance P2 P3 = 1.34
sketch "Sketch12" plane through (0, 0, 4) normal (0, 0, 1) x axis (-1, 0, 0)
  line L1 (-13.0116, 0.0072) -> (-11.6716, 0.0072)
  point P2 (-11.6716, 0.0072)
  point P3 (-13.0116, 0.0072)
  horizontal L1
  dimension "d23" distance P2 P3 = 1.34
sketch "Sketch13" plane through (0, 0, 4) normal (0, 0, 1) x axis (-1, 0, 0)
  line L1 (-15.4938, -0.0296) -> (-14.1538, -0.0296)
  point P2 (-14.1538, -0.0296)
  point P3 (-15.4938, -0.0296)
  horizontal L1
  dimension "d24" distance P2 P3 = 1.34
sketch "Sketch14" plane through (0, 0, 4) normal (0, 0, 1) x axis (-1, 0, 0)
  line L1 (-17.9193, -0.0235) -> (-16.5793, -0.0235)
  point P2 (-16.5793, -0.0235)
  point P3 (-17.9193, -0.0235)
  horizontal L1
  dimension "d25" distance P2 P3 = 1.34
extrude "Extrude5" cut sketch "Sketch9" profile of C1 C2 C3 C4 C5 against normal blind 6
component_from_bodies "Body->Comp"
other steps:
base_feature "Base Feature"
create_component "CreateComponent1"
remove_body "RemoveBody1"

design "FinalprojectPCBnew"
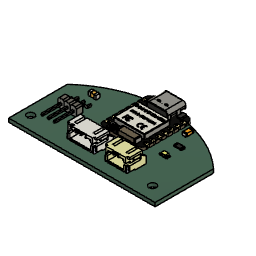
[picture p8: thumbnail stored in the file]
description: KiCad electronic assembly
part number: FinalprojectPCBnew2 1
description: Part Number
part number: Terminator_Left
part number: Terminator_Right
part number: Capacitor_Body
part number: C_1206
part number: FinalprojectPCBnew2 1.2.1
part number: FinalprojectPCBnew2 1.2.2
part number: Header_SMD_01x03_P2.54mm_Horizontal_Male
part number: SxB-PH-SM4-TB white_4
part number: S4B-PH-SM4-TB
base_feature "Base Feature1"
base_feature "Base Feature1"
base_feature "Base Feature1"
base_feature "Base Feature1"
base_feature "Base Feature1"
base_feature "Base Feature1"
base_feature "Base Feature1"
base_feature "Base Feature1"
base_feature "Base Feature1"
base_feature "Base Feature1"
base_feature "Base Feature1"
base_feature "Base Feature1"
base_feature "Base Feature1"
base_feature "Base Feature1"
base_feature "Base Feature1"
base_feature "Base Feature1"
base_feature "Base Feature1"
base_feature "Base Feature1"
base_feature "Base Feature1"
base_feature "Base Feature1"
base_feature "Base Feature1"
base_feature "Base Feature1"
base_feature "Base Feature1"
base_feature "Base Feature1"
base_feature "Base Feature1"
base_feature "Base Feature1"
base_feature "Base Feature1"
base_feature "Base Feature1"
base_feature "Base Feature1"
base_feature "Base Feature1"
base_feature "Base Feature1"
base_feature "Base Feature1"
base_feature "Base Feature1"
base_feature "Base Feature1"
base_feature "Base Feature1"
base_feature "Base Feature1"
base_feature "Base Feature1"
base_feature "Base Feature1"
base_feature "Base Feature1"
base_feature "Base Feature1"
base_feature "Base Feature1"
base_feature "Base Feature1"
base_feature "Base Feature1"
base_feature "Base Feature1"
base_feature "Base Feature1"
base_feature "Base Feature1"
base_feature "Base Feature1"
base_feature "Base Feature1"
base_feature "Base Feature1"
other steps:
create_component "CreateComponent1"
create_component "CreateComponent1"
create_component "CreateComponent2"
create_component "CreateComponent3"
create_component "CreateComponent2"
create_component "CreateComponent1"
create_component "CreateComponent2"
create_component "CreateComponent3"
create_component "CreateComponent1"
create_component "CreateComponent4"
create_component "CreateComponent5"
create_component "CreateComponent1"
create_component "CreateComponent2"
create_component "CreateComponent3"
create_component "CreateComponent6"
create_component "CreateComponent1"
create_component "CreateComponent2"
create_component "CreateComponent3"
create_component "CreateComponent4"
create_component "CreateComponent7"
create_component "CreateComponent1"
create_component "CreateComponent2"
create_component "CreateComponent3"
create_component "CreateComponent4"
create_component "CreateComponent8"
create_component "CreateComponent1"
create_component "CreateComponent1"
create_component "CreateComponent1"
create_component "CreateComponent1"
create_component "CreateComponent1"
create_component "CreateComponent2"
create_component "CreateComponent3"
create_component "CreateComponent4"
create_component "CreateComponent5"
create_component "CreateComponent6"
create_component "CreateComponent7"
create_component "CreateComponent8"
create_component "CreateComponent9"
create_component "CreateComponent10"
create_component "CreateComponent11"
create_component "CreateComponent12"
create_component "CreateComponent13"
create_component "CreateComponent14"
create_component "CreateComponent15"
create_component "CreateComponent16"
create_component "CreateComponent17"
create_component "CreateComponent18"
create_component "CreateComponent19"
create_component "CreateComponent20"
create_component "CreateComponent21"
create_component "CreateComponent22"
create_component "CreateComponent23"
create_component "CreateComponent24"
create_component "CreateComponent2"
create_component "CreateComponent3"
create_component "CreateComponent1"
create_component "CreateComponent2"
create_component "CreateComponent4"
create_component "CreateComponent5"
create_component "CreateComponent2"
create_component "CreateComponent9"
